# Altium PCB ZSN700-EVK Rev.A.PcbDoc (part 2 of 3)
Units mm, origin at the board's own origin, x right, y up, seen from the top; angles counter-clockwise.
Board outline 122.05 x 75.06 mm, 2 copper layers (Top Layer, Bottom Layer), stack 0 mm thick; 172 components, 135 nets, 573 pads, 599 vias.
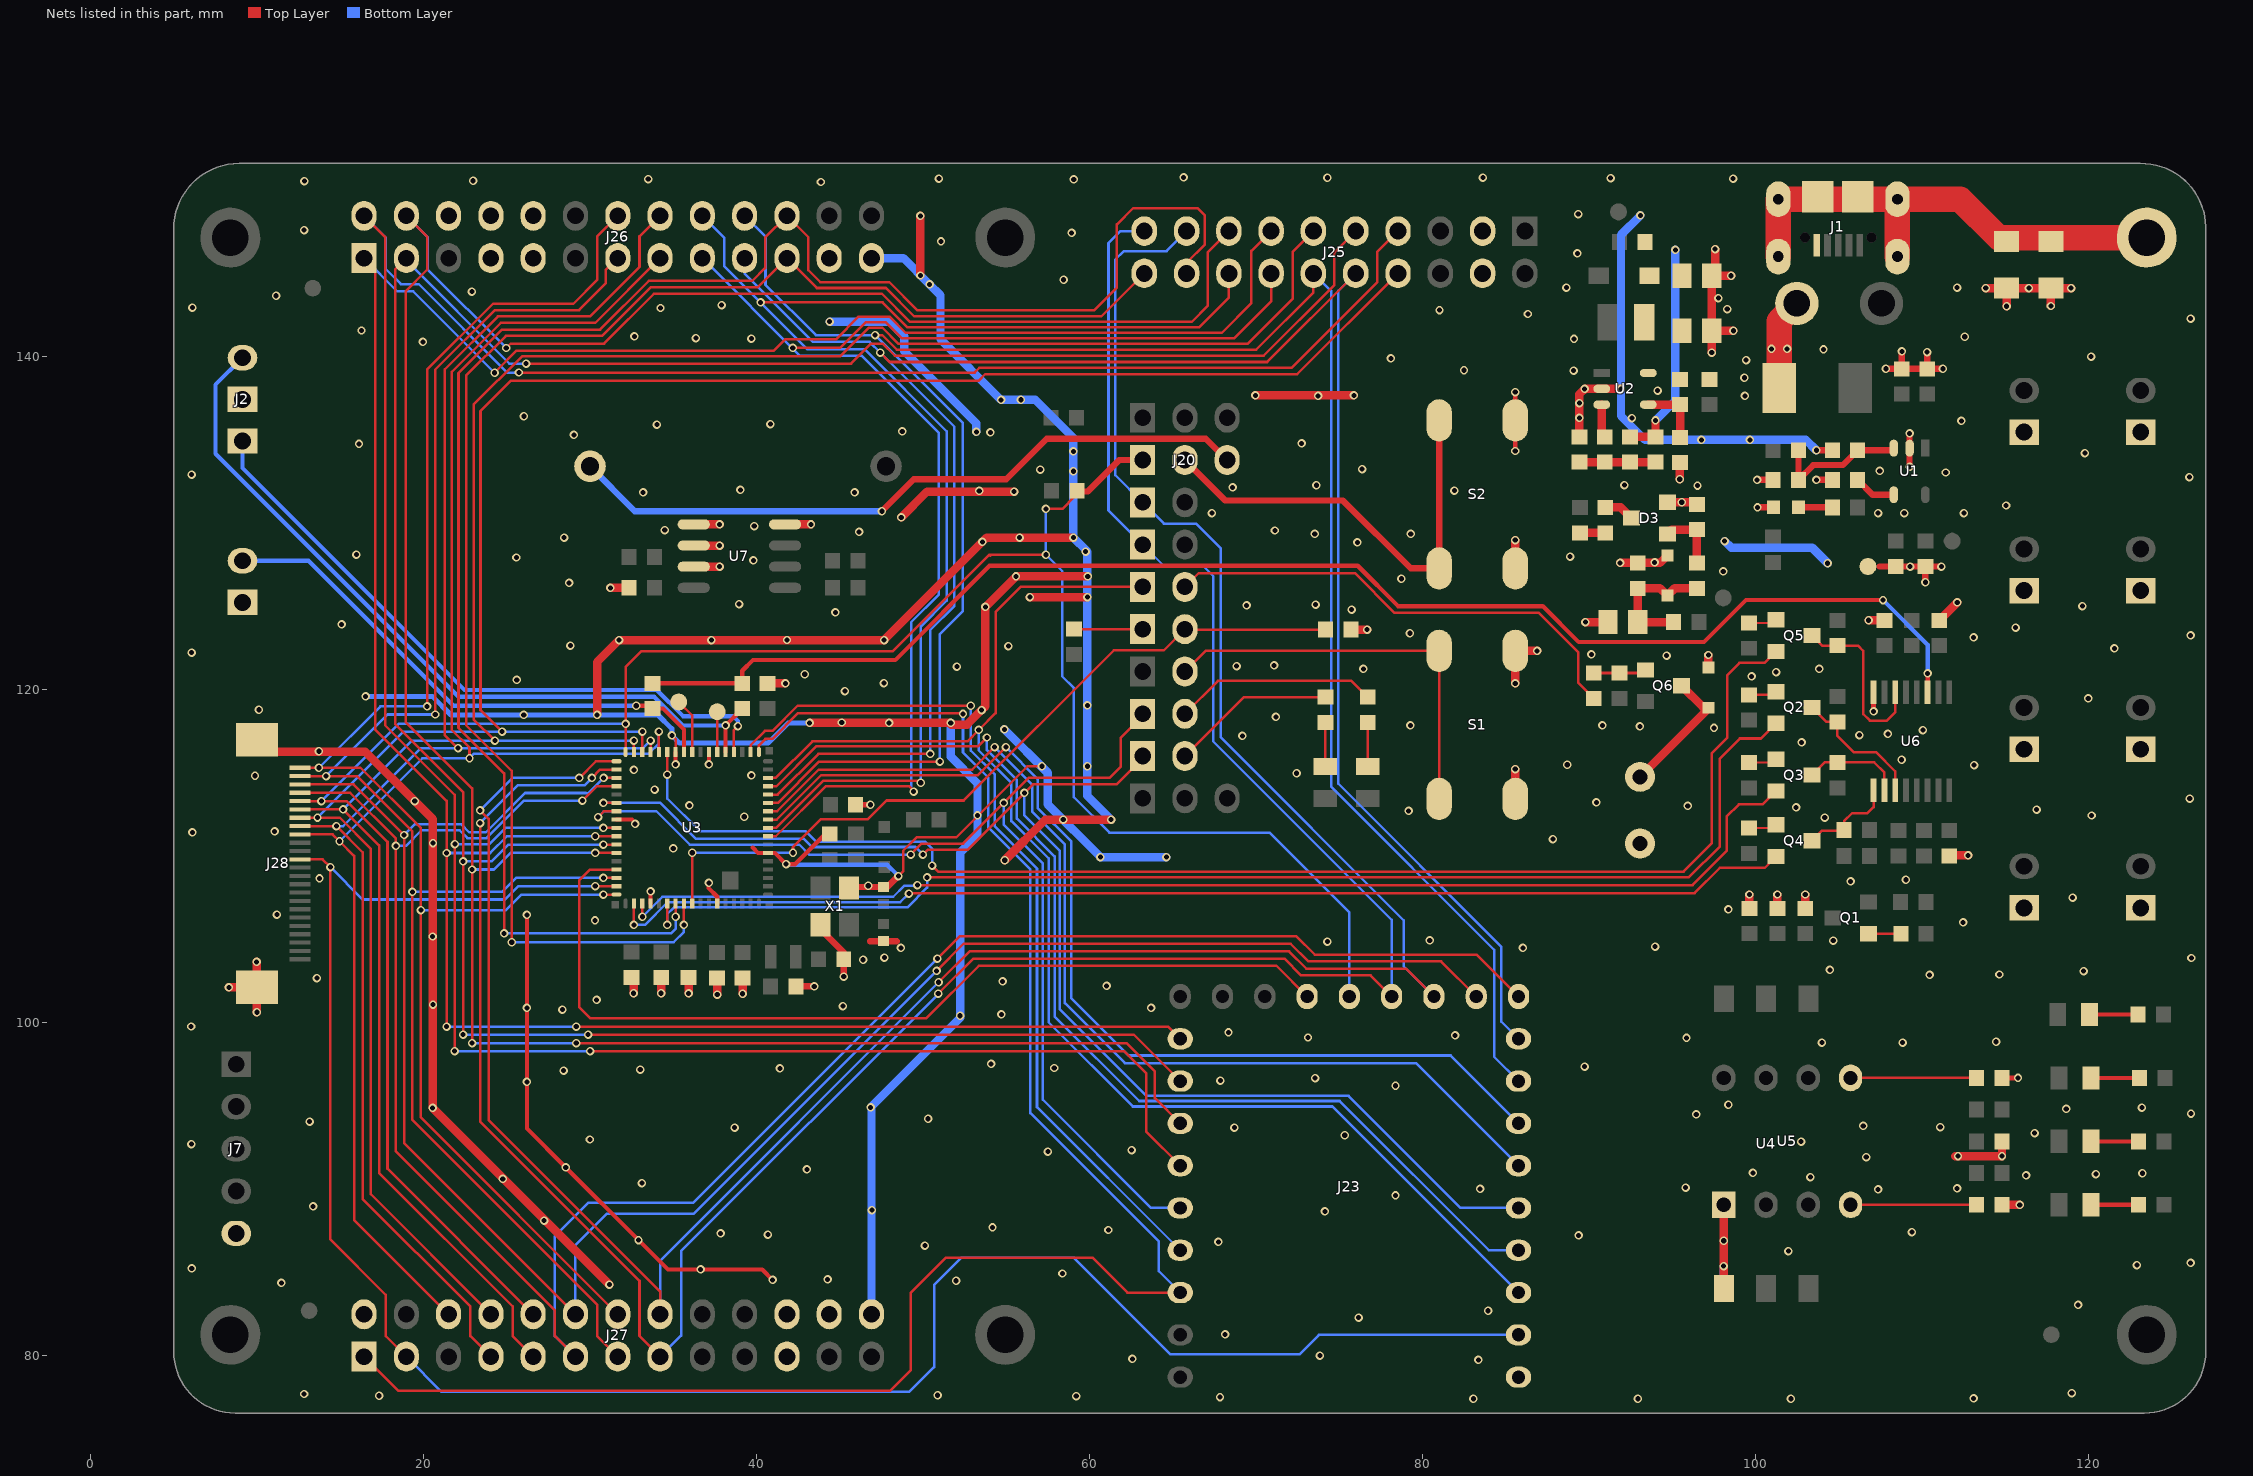
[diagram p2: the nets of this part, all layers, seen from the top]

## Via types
v1: diameter 0.508, hole 0.305, Top Layer to Bottom Layer, tented both sides, 599 vias

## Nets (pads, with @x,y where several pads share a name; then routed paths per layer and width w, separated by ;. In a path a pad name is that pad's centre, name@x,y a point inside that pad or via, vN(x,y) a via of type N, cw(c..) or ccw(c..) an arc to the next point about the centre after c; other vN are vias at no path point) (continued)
AM4051_ENN: Q5.2 U3.63 | length 82.6
  Top Layer w0.152: v1(34.643,114.909) U3.63@34.643,116.252 ; v1(50.552,109.438) 50.907,109.083 95.68,109.083 97.381,110.785 97.381,116.195 98.296,117.109 98.296,120.87 99.041,121.615 100.549,121.615 Q5.2@101.24,122.306
  Bottom Layer w0.152: v1(34.643,114.909) 34.643,113.47 36.606,111.507 42.954,111.507 43.6,110.861 50.149,110.861 50.552,110.458 v1(50.552,109.438)
AM4051_ENN1: Q5.3 R34.1 U6.6 | length 10.7
  Top Layer w0.152: Q5.3@103.399,123.256 104.009,122.646 R34.1@104.923,122.646 106.161,122.646 106.477,122.33 106.477,118.546 106.874,118.149 107.895,118.149 108.393,118.647 U6.6@108.393,119.856
AM4051_S1: Q2.2 U3.23 | length 76.7
  Top Layer w0.152: v1(34.643,105.88) U3.23@34.643,107.152 ; v1(50.247,108.727) 95.992,108.727 97.864,110.599 97.864,115.865 99.072,117.072 100.325,117.072 Q2.2@101.24,117.988
  Bottom Layer w0.152: v1(34.643,105.88) 34.643,106.519 35.056,106.932 49.062,106.932 50.247,108.116 v1(50.247,108.727)
AM4051_S2: Q3.2 U3.20 | length 73.2
  Top Layer w0.152: v1(33.143,106.369) U3.20@33.143,107.152 ; v1(49.663,108.27) 96.221,108.27 98.27,110.319 98.27,112.385 99.001,113.115 100.432,113.115 Q3.2@101.24,113.924
  Bottom Layer w0.152: v1(33.143,106.369) 34.345,107.57 48.216,107.57 48.873,108.227 49.62,108.227 v1(49.663,108.27)
AM4051_S3: Q4.2 U3.19 | length 71.6
  Top Layer w0.152: v1(32.643,105.88) U3.19@32.643,107.152 ; v1(49.155,107.762) 49.155,107.775 49.166,107.787 96.348,107.787 97.872,109.311 100.565,109.311 Q4.2@101.24,109.987
  Bottom Layer w0.152: v1(32.643,105.88) 33.301,105.88 34.658,107.237 48.629,107.237 v1(49.155,107.762)
AM4051_S11: Q2.3 R29.1 U6.11 | length 8.2
  Top Layer w0.152: Q2.3@103.399,118.938 104.263,118.074 R29.1@104.923,118.074 104.923,117.235 105.903,116.256 107.243,116.256 108.393,115.105 U6.11@108.393,113.956
AM4051_S22: Q3.3 R30.1 U6.10 | length 6
  Top Layer w0.152: Q3.3@103.399,114.874 104.161,115.636 R30.1@104.923,115.636 107.135,115.636 107.743,115.028 U6.10@107.743,113.956
AM4051_S33: Q4.3 R33.1 U6.9 | length 5.9
  Top Layer w0.152: Q4.3@103.399,110.937 104.009,111.547 105.332,111.547 R33.1@105.332,111.572 105.332,112.105 105.814,112.588 106.729,112.588 107.093,112.953 U6.9@107.093,113.956
AM4051_TX: R12.2 R13.2 U6.3 | length 86.9
  Top Layer w0.254: R13.2@33.762,120.386 R12.2@39.147,120.386 39.147,121.14 39.799,121.793 48.342,121.793 53.996,127.447 76.112,127.447 78.537,125.023 87.224,125.023 89.383,122.864 96.911,122.864 99.433,125.386 v1(107.663,125.386) ; U6.3@110.343,119.856 v1(110.343,120.98)
  Bottom Layer w0.254: v1(107.663,125.386) 110.343,122.706 v1(110.343,120.98)
ANT_TX1: T5.1 U3.57 | length 2.4
  Top Layer w0.152: T5.1@37.639,118.685 37.643,118.681 U3.57@37.643,116.252
ANT_TX2: T6.1 U3.60 | length 3.4
  Top Layer w0.152: T6.1@35.328,119.27 36.143,118.454 U3.60@36.143,116.252
BEEP: J18.2 R43.1 | length 29.1
  Top Layer w0.152: J18.2@65.731,126.178 66.565,127.012 75.938,127.012 78.334,124.616 86.995,124.616 89.35,122.262 89.35,120.427 R43.1@90.293,119.483
BOOT0: J8.2 R17.2 U3.26 | length 46.9
  Top Layer w0.152: v1(36.142,110.21) 36.142,107.154 U3.26@36.143,107.152 ; v1(42.195,110.21) 42.195,110.553 43.87,112.228 46.69,112.228 47.812,113.35 52.44,113.35 61.458,122.368 64.461,122.368 J8.2@65.731,123.638 65.758,123.612 R17.2@74.174,123.612
  Bottom Layer w0.152: v1(36.142,110.21) v1(42.195,110.21)
CAN0_RX_AWORKS: J26.9
CAN0_TX_AWORKS: J26.10
CAN1_RX_AWORKS: J26.7
CAN1_TX_AWORKS: J26.8
COM0: J26.14 J27.14 J28.1 U3.17 | length 100.1
  Top Layer w0.152: J28.1@12.575,115.316 v1(13.722,115.316) 16.215,115.316 19.839,111.691 v1(19.839,106.768) 19.839,94.321 J27.14@31.67,82.49 ; v1(20.224,119.006) 20.224,139.224 24.186,143.187 29.004,143.187 30.435,144.617 30.435,147.231 J26.14@31.67,148.466 ; v1(30.806,107.702) U3.17@31.59,107.702
  Bottom Layer w0.152: v1(13.722,115.316) 17.412,119.006 v1(20.224,119.006) ; v1(19.839,106.768) 24.946,106.768 25.881,107.702 v1(30.806,107.702)
COM1: J26.13 J27.13 J28.2 U3.15 | length 100.4
  Top Layer w0.152: J28.2@12.575,114.816 v1(14.153,114.816) 16.008,114.816 19.339,111.484 v1(19.339,107.86) 19.339,94.169 30.435,83.073 30.435,81.186 J27.13@31.67,79.95 ; v1(20.707,118.514) 20.707,139.224 24.288,142.806 29.342,142.806 30.943,144.407 30.943,145.199 J26.13@31.67,145.926 ; v1(30.806,108.702) U3.15@31.59,108.702
  Bottom Layer w0.152: v1(14.153,114.816) 17.852,118.514 v1(20.707,118.514) ; v1(19.339,107.86) 24.718,107.86 25.56,108.702 v1(30.806,108.702)
COM2: J23.11 J27.12 J28.3 U3.3 | length 122.2
  Top Layer w0.152: J28.3@12.575,114.316 15.801,114.316 v1(18.839,111.277) 18.839,92.781 J27.12@29.13,82.49 ; v1(30.821,114.702) U3.3@31.59,114.702 ; v1(50.816,103.121) 52.442,104.746 72.086,104.746 73.15,103.683 81.125,103.683 J23.11@83.232,101.576
  Bottom Layer w0.152: v1(18.839,111.277) 19.493,111.931 22.256,111.931 22.746,111.441 23.745,111.441 26.103,113.799 29.735,113.799 29.738,113.796 29.914,113.796 v1(30.821,114.702) ; J27.12@29.13,82.49 29.13,86.644 31.028,88.542 36.238,88.542 v1(50.816,103.121)
COM3: J23.10 J27.11 J28.4 U3.4 | length 132.2
  Top Layer w0.152: J28.4@12.575,113.816 15.593,113.816 18.339,111.07 v1(18.339,110.624) 18.339,92.273 27.895,82.718 27.895,81.186 J27.11@29.13,79.95 ; v1(29.546,113.342) 30.406,114.202 U3.4@31.59,114.202 ; v1(50.867,103.857) 52.213,105.203 72.416,105.203 73.531,104.089 83.259,104.089 J23.10@85.772,101.576
  Bottom Layer w0.152: v1(18.339,110.624) 18.943,110.624 19.868,111.55 22.18,111.55 22.637,111.093 23.791,111.093 26.041,113.342 v1(29.546,113.342) ; J27.11@29.13,79.95 27.895,81.186 27.895,87.187 29.911,89.203 36.213,89.203 v1(50.867,103.857)
CZ_RX: J2.1 U3.55 | length 39.6
  Top Layer w0.152: U3.55@38.643,116.252 38.643,117.572 v1(38.884,117.812)
  Bottom Layer w0.254: J2.1@9.13,134.942 9.13,133.318 22.459,119.989 34.008,119.989 35.583,118.415 38.588,118.415 38.884,118.119 v1(38.884,117.812)
CZ_TX1: J2.3 J4.2 R12.1 U3.56 | length 46.8
  Top Layer w0.254: U3.56@38.143,116.252 v1(38.143,117.858) R12.1@39.147,118.862
  Bottom Layer w0.254: J2.3@9.13,139.942 7.515,138.326 7.515,134.172 22.104,119.583 33.856,119.583 35.581,117.858 v1(38.143,117.858)
CZ_TX2: J3.2 R13.1 U3.61 | length 32.1
  Top Layer w0.152: R13.1@33.584,119.04 R13.1@33.762,118.862
  Top Layer w0.254: v1(32.78,119.04) R13.1@33.584,119.04 ; R13.1@33.775,118.874 34.388,118.874 35.643,117.619 U3.61@35.643,116.252
  Bottom Layer w0.254: J3.2@9.13,127.75 13.099,127.75 21.809,119.04 v1(32.78,119.04)
EARTH1: C1.1 HOLE4.1 J1.6 J1.7 J1.8 J1.9 J1.10 J1.11 R1.2 | length 30
  Top Layer w1.524: J1.7@101.374,146.014 J1.9@101.374,149.464 J1.8@108.524,149.464 ; J1.6@108.524,146.014 J1.8@108.524,149.464 ; HOLE4.1@123.5,147.158 114.6,147.158 112.294,149.464 J1.8@108.524,149.464
ERR_AWORKS: J26.6
GND: BZ1.2 C1.2 C2.1 C3.1 C4.1 C5.1 C6.1 C7.1 C9.2 C10.2 C12.2 C13.1 C14.2 C15.2 C16.2 C17.2 C18.2 C19.2 C20.1 C21.2 C22.2 C23.2 C24.2 C25.2 C26.2 C27.2 C28.2 C29.2 C30.2 D1.2 D3.2 D4.2 D6.1 J1.5 J2.2 J3.1 J4.1 J7.5 J9.1 J10.1 J11.1 J12.1 J13.1 J14.1 J15.1 J16.1 J23.1 J25.3 J25.4 J26.23 J26.25 J27.21 J27.26 J28.25 J28.26 J29.2 LED1.2 R1.1 R4.2 R8.1 R9.1 R11.1 R17.1 R18.2 R25.1 R26.1 R27.1 R40.1 S1.2 S1.3 S2.1 S2.4 T2.1 T8.1 U1.2 U2.2 U3.8 U3.21 U3.29 U3.40 U3.58 U3.62 U4.6 U5.1 U6.8 U7.4 U7.5 U7.6 U7.7 X1.2 X1.4 | length 469.7
  Top Layer w0.152: v1(34.915,117.262) 35.143,117.034 U3.62@35.143,116.252 ; v1(48.525,108.813) 48.808,109.096 48.808,110.33 49.618,111.14 52,111.14 56.267,115.407 v1(57.139,115.407)
  Top Layer w0.254: v1(26.21,106.477) v1(26.21,100.889) v1(26.21,96.444) 26.21,93.65 v1(28.547,91.313) v1(32.916,86.944) 34.682,85.178 40.346,85.178 v1(40.968,84.556) ; U3.8@31.59,112.202 32.526,112.202 ; U3.21@33.643,107.152 v1(33.643,107.89) ; v1(35.143,115.517) U3.62@35.143,116.252 ; 37.113,108.126 37.113,108.1 37.643,107.57 U3.29@37.643,107.152 ; v1(37.143,115.515) U3.58@37.143,116.252 ; 39.776,110.519 40.093,110.202 41.103,110.202 v1(41.781,109.525) 42.322,109.525 44.13,111.332 C19.2@44.399,111.332 ; X1.2@45.549,108.092 X1.2@45.61,108.153 ; v1(85.576,134.34) S2.1@85.576,136.183 v1(85.576,137.877)
  Top Layer w0.305: C14.2@45.958,113.096 v1(46.847,113.096) ; U5.1@98.095,89.066 U5.1@98.098,89.063 ; v1(107.093,118.696) U6.8@107.093,119.856 ; R26.1@114.808,96.686 v1(115.77,96.686)
  Top Layer w0.381: C22.2@42.379,102.185 v1(43.471,102.185) ; X1.4@43.849,105.892 43.849,105.617 45.243,104.223 C25.2@45.243,103.81 v1(45.243,102.776) ; X1.2@45.61,108.153 C21.2@47.631,108.153 47.864,108.153 v1(48.525,108.813) ; 46.823,104.902 C20.1@47.631,104.902 48.426,104.902 ; v1(100.099,132.607) R4.2@101.063,132.607 ; v1(100.123,130.956) LED1.2@101.087,130.956 ; v1(103.655,132.607) C6.1@104.619,132.607 ; v1(103.655,134.385) C7.1@104.619,134.385 ; 107.464,127.4 C4.1@108.429,127.4 v1(109.293,127.4) C5.1@110.207,127.4 ; v1(107.838,139.28) C3.1@108.792,139.28 ; v1(108.792,140.321) C3.1@108.792,139.28 ; v1(109.257,133.384) U1.2@109.257,134.512 v1(109.257,135.4) ; v1(110.207,126.46) C5.1@110.207,127.4 ; v1(110.316,140.285) C2.1@110.316,139.28 ; v1(111.172,127.4) C5.1@110.207,127.4 ; v1(111.256,139.28) C2.1@110.316,139.28 ; C3.1@108.792,139.28 C2.1@110.316,139.28
  Top Layer w0.508: v1(8.317,102.126) J28.26@10,102.126 ; v1(9.982,103.661) 9.982,102.144 J28.26@10,102.126 ; v1(10,100.631) J28.26@10,102.126 ; J28.25@10.597,116.373 10.699,116.271 16.516,116.271 v1(19.477,113.309) 20.554,112.232 v1(20.554,105.181) v1(20.554,94.884) v1(31.171,84.267) ; v1(30.427,118.489) 30.427,121.666 v1(31.748,122.987) v1(47.667,122.987) 53.818,129.137 v1(59.03,129.137) ; v1(31.227,126.124) C30.2@32.35,126.124 ; v1(32.619,101.774) C18.2@32.619,102.733 ; v1(34.277,101.774) C15.2@34.277,102.733 ; v1(35.923,101.769) C16.2@35.923,102.728 ; U7.7@36.235,127.394 v1(37.787,127.394) ; U7.6@36.235,128.664 v1(37.787,128.664) ; U7.5@36.235,129.934 v1(37.787,129.934) ; v1(37.643,101.694) C23.2@37.643,102.653 ; v1(39.163,101.744) C24.2@39.163,102.702 ; C17.2@40.671,120.386 v1(41.738,120.386) ; U7.4@41.723,129.934 v1(43.275,129.934) ; v1(43.192,118.009) 43.195,118.006 v1(51.667,118.006) ; v1(48.697,130.353) 50.251,131.906 v1(55.474,131.906) ; v1(49.84,144.881) v1(49.84,148.463) ; v1@51.689,117.908 52.655,117.908 v1(53.523,118.776) 53.752,119.005 v1(53.752,124.976) v1(55.588,126.812) v1(59.899,126.812) ; v1(54.914,109.762) 57.359,112.207 v1(58.426,112.207) v1(61.296,112.207) ; v1(56.419,125.567) v1(59.872,125.567) ; v1(69.969,137.68) v1(75.888,137.68) ; R17.1@75.698,123.612 v1(76.671,123.612) ; S1.2@85.576,113.45 v1(85.576,115.235) ; v1(85.576,120.38) S1.3@85.576,122.34 v1(86.893,122.34) ; S2.4@85.576,127.293 v1(85.576,128.99) ; R9.1@89.426,135.19 v1(89.426,136.333) v1(89.426,137.222) 89.426,137.756 v1(89.746,138.076) U2.2@90.772,138.076 v1(91.925,138.076) ; v1(89.79,124.065) C12.2@91.153,124.065 ; v1(91.873,127.621) R11.1@92.931,127.621 94.265,127.621 D4.2@94.709,128.066 ; D3.2@94.709,131.264 v1(95.576,131.264) 96.365,131.264 C13.1@96.487,131.142 ; v1(95.453,132.643) 95.453,133.623 R8.1@95.471,133.641 ; D6.1@97.177,121.337 v1(97.177,122.089) ; v1(97.376,140.245) C10.2@97.376,141.566 ; v1(97.573,146.465) 97.573,145.065 C9.2@97.376,144.868 ; U4.6@98.098,84.037 v1(98.098,86.909) U5.1@98.098,89.063 ; v1(98.544,144.868) C9.2@97.376,144.868 ; v1(98.671,141.566) C10.2@97.376,141.566 ; R18.2@99.64,106.873 v1(99.64,107.705) ; C27.2@101.316,106.873 v1(101.316,107.705) ; C26.2@102.993,106.873 v1(102.993,107.705) ; v1(106.802,124.174) C29.2@107.743,124.174 ; R40.1@111.045,124.174 v1(112.123,125.251) ; C28.2@111.643,110.019 111.682,110.058 v1(112.774,110.058) ; v1@112.014,91.986 v1(114.808,91.986) R27.1@114.808,92.876 ; v1(113.834,144.121) C1.2@115.082,144.121 ; R25.1@114.808,89.066 v1(115.874,89.066) ; v1(115.082,143.037) C1.2@115.082,144.121 ; v1(117.749,143.051) R1.1@117.749,144.121 ; v1(118.965,144.121) R1.1@117.749,144.121 ; C10.2@97.376,141.566 C9.2@97.376,144.868 ; C1.2@115.082,144.121 R1.1@117.749,144.121
  Top Layer w1.524: D1.2@101.426,138.137 101.426,142.142 J29.2@102.489,143.206
  Bottom Layer w0.254: v1(41.781,109.525) 41.816,109.489 47.849,109.489 v1(48.525,108.813)
  Bottom Layer w0.305: v1(16.525,119.606) 20.531,119.606 21.648,118.489 v1(26.025,118.489) v1(30.427,118.489) 34.088,118.489 34.915,117.661 v1(34.915,117.262) 35.384,116.793 40.686,116.793 41.903,118.009 v1(43.192,118.009)
  Bottom Layer w0.508: v1(44.389,142.111) 47.987,142.111 48.87,141.228 48.87,140.339 53.213,135.995 v1(53.213,135.487) ; J27.26@46.91,82.49 46.91,94.976 52.228,100.294 v1(52.228,100.421) 52.228,110.212 53.276,111.259 53.276,114.377 51.667,115.986 v1(51.667,118.006) ; J26.25@46.91,145.926 48.821,145.926 v1(50.399,144.348) 51.054,143.693 51.054,141.052 v1(54.692,137.414) 56.749,137.414 59.035,135.128 59.03,135.122 v1(59.03,129.137) 59.872,128.295 v1(59.872,125.567) v1(59.872,119.066) 59.872,113.631 v1(61.296,112.207) ; v1(54.895,117.617) 57.494,115.018 57.494,113.113 v1(60.661,109.946) v1(64.623,109.946) ; v1(93.091,148.492) 91.925,147.326 91.925,136.45 93.37,135.005 v1(99.67,135.005) 103.035,135.005 v1(103.655,134.385) ; v1(98.091,85.385) 98.098,85.377 T8.1@98.098,84.037 ; v1(98.146,128.934) 98.552,128.528 103.412,128.528 v1(104.341,127.599)
  other v1: 83.056,77.419 92.936,77.419 102.131,77.419 113.104,77.444 67.841,77.521 59.207,77.575 17.335,77.598 50.876,77.626 12.827,77.702 119,77.758 83.36,79.756 62.583,79.807 73.835,80.01 68.146,81.28 76.172,82.296 83.945,82.702 119.378,83.058 11.467,84.38 51.991,84.506 44.27,84.582 58.369,84.941 36.65,85.191 6.083,85.243 122.911,85.449 126.134,85.572 101.981,86.288 50.112,86.614 67.739,86.842 89.383,87.227 40.688,87.274 37.844,87.35 109.398,87.431 61.135,87.554 54.176,87.706 27.252,88.112 74.14,88.671 46.937,88.747 13.372,88.977 78.382,89.636 107.366,89.996 83.462,90.017 112.116,90.047 95.809,90.098 33.119,90.373 24.763,90.627 103.302,90.733 116.256,90.834 120.447,90.91 123.241,90.961 99.847,90.987 43.028,91.19 106.655,91.926 112.166,91.986 57.5,92.258 62.532,92.354 6.057,92.711 102.743,92.866 29.995,92.989 75.334,93.243 116.764,93.374 38.684,93.704 68.705,93.7 111.1,93.73 106.477,93.806 13.157,94.06 50.315,94.234 96.444,94.492 126.162,94.543 118.669,94.822 123.215,94.898 46.861,94.92 98.374,95.076 78.382,96.215 67.866,96.52 73.556,96.672 28.42,97.129 33.02,97.184 41.402,97.26 57.884,97.282 89.738,97.362 54.1,97.536 103.988,98.81 108.839,98.81 114.452,98.861 95.86,99.089 73.127,99.115 81.966,99.242 68.351,99.419 6.045,99.775 54.709,100.508 28.344,100.787 63.701,100.889 45.187,100.994 20.572,101.092 30.404,101.375 61.034,102.209 54.785,102.489 13.603,102.682 110.465,102.874 114.656,102.899 119.71,103.102 104.47,103.179 46.402,103.786 126.187,103.89 47.68,103.909 48.67,104.493 86.027,104.495 93.978,104.572 74.293,104.876 104.673,104.931 80.439,104.953 112.471,106.023 30.302,106.15 11.19,106.492 98.372,106.807 119.047,107.518 46.714,108.227 37.139,108.405 105.715,108.487 109.042,108.589 13.756,108.676 35.001,110.468 20.572,110.788 87.833,111.027 6.121,111.434 11.063,111.496 32.715,111.942 104.165,112.323 39.268,112.373 53.276,112.451 120.193,112.45 79.172,112.729 116.888,112.801 102.438,112.932 95.933,113.03 35.966,113.059 90.449,113.237 126.086,113.466 33.884,113.999 9.881,114.837 39.7,114.863 72.438,114.986 32.639,115.193 59.872,115.407 113.132,115.472 88.697,115.498 108.786,115.798 13.714,116.306 102.768,116.844 69.19,117.225 106.248,117.276 107.95,117.352 110.058,117.58 97.511,117.707 93.063,117.805 79.271,117.856 90.803,117.856 47.967,118.009 45.122,118.035 71.196,118.368 10.109,118.8 119.99,119.485 45.314,119.917 47.65,120.4 25.601,120.599 99.769,120.802 42.901,120.933 101.244,121.06 76.452,121.259 103.833,121.259 52.042,121.386 68.834,121.416 71.095,121.467 94.666,122.051 90.145,122.127 6.071,122.229 121.564,122.483 55.132,122.621 28.827,122.656 37.287,122.987 41.834,122.991 113.106,123.143 126.136,123.27 79.248,123.397 115.632,123.732 15.088,123.93 44.744,124.653 75.743,124.819 119.634,125.023 69.441,125.069 73.581,125.12 38.964,125.15 28.75,126.416 78.738,126.67 98.069,127.105 93.947,127.652 39.816,127.777 25.578,127.944 88.875,127.994 15.974,128.117 59.766,128.299 76.096,128.854 53.569,128.888 28.448,129.137 55.804,129.137 73.531,129.362 79.296,129.362 46.166,129.479 71.143,129.565 34.493,129.595 39.867,129.835 67.358,130.607 107.366,130.611 108.941,130.611 112.526,130.605 115.062,131.068 33.194,131.857 45.894,131.857 53.38,131.943 81.915,131.957 39.036,132.009 68.603,132.156 96.52,132.262 73.632,132.283 92.126,132.287 126.06,132.77 6.071,132.922 111.43,133.049 59.03,133.125 107.467,133.151 57.045,133.228 76.375,133.248 119.786,134.217 59.03,134.319 16.127,134.772 72.743,134.798 96.749,135.005 29.032,135.31 54.047,135.463 48.757,135.524 34.025,135.931 40.832,135.956 112.37,136.148 92.581,136.322 26.035,136.427 55.876,137.419 73.729,137.654 99.365,137.646 94.13,137.973 99.339,138.739 89.078,139.17 82.497,139.192 99.441,139.805 78.103,139.903 120.167,140.009 104.089,140.44 100.965,140.476 101.905,140.476 19.962,140.894 89.103,141.075 39.69,141.095 36.362,141.12 112.573,141.202 32.668,141.222 16.279,141.579 126.136,142.295 86.332,142.57 81.024,142.799 98.31,142.858 34.235,142.931 6.121,142.955 37.912,143.101 97.776,143.519 11.151,143.666 22.908,143.916 116.422,144.124 88.646,144.149 112.116,144.149 58.449,144.625 89.306,146.206 51.083,146.937 58.932,147.445 12.827,147.603 89.357,148.568 43.866,150.499 12.852,150.55 22.987,150.575 59.055,150.651 33.503,150.677 50.956,150.696 98.665,150.707 91.299,150.732 74.295,150.753 83.628,150.758 65.659,150.778
GPIO4_AWORKS: J20.1 J23.14 J27.10 J28.5 R48.1 U3.68 | length 141.3
  Top Layer w0.152: J28.5@12.575,113.316 v1(13.873,113.316) 15.386,113.316 17.839,110.863 17.839,91.241 J27.10@26.59,82.49 ; U3.68@32.143,116.252 v1(32.143,117.947) 32.143,121.358 33.102,122.316 48.194,122.316 53.995,128.117 54.048,128.065 54.091,128.108 v1(57.379,128.108) ; v1(57.379,130.865) 58.37,130.865 59.106,131.6 ccw(c58.748,131.958) 59.252,131.906 ccw(c58.748,131.958) R48.1@59.254,131.958
  Top Layer w0.381: R48.1@59.252,131.906 59.893,131.906 61.786,133.798 J20.1@63.191,133.798
  Bottom Layer w0.152: v1(13.873,113.316) 18.505,117.947 v1(32.143,117.947) ; v1(57.379,130.865) v1(57.379,128.108) 58.365,127.121 58.365,120.808 59.069,120.104 59.069,113.545 61.194,111.42 70.813,111.42 75.612,106.621 J23.14@75.612,101.576
GPIO5_AWORKS: J25.11 J27.9 J28.6 U3.67 | length 138
  Top Layer w0.152: J28.6@12.575,112.816 v1(15.179,112.816) 17.339,110.656 17.339,90.987 25.355,82.972 25.355,81.186 J27.9@26.59,79.95 ; v1(24.288,116.949) 23.018,118.219 23.018,137.124 25.939,140.045 45.041,140.045 46.751,141.755 47.556,141.755 48.533,140.778 69.503,140.778 72.218,143.493 72.218,146.315 J25.11@73.453,147.55 ; U3.67@32.643,116.252 v1(32.643,116.949)
  Bottom Layer w0.152: v1(15.179,112.816) 19.312,116.949 v1(24.288,116.949) v1(32.643,116.949)
GPIO6_AWORKS: J25.8 J27.8 J28.7 U3.66 | length 137.2
  Top Layer w0.152: J28.7@12.575,112.316 v1(13.636,112.316) 14.972,112.316 16.839,110.449 16.839,89.701 J27.8@24.05,82.49 ; v1(24.72,117.482) 23.424,118.777 23.424,136.743 25.253,138.572 53.361,138.572 53.738,138.95 72.472,138.95 J25.8@78.533,145.01 ; U3.66@33.143,116.252 v1(33.143,117.482)
  Bottom Layer w0.152: v1(13.636,112.316) 18.802,117.482 v1(24.72,117.482) v1(33.143,117.482)
GPIO7_AWORKS: J26.16 J27.7 J28.8 U3.65 | length 100.5
  Top Layer w0.152: J28.8@12.575,111.816 v1(14.765,111.816) 16.339,110.242 16.339,89.422 22.815,82.946 22.815,81.186 J27.7@24.05,79.95 ; v1@22.068,116.481 21.291,117.258 21.291,139.25 24.466,142.425 29.995,142.425 32.975,145.405 32.975,147.231 J26.16@34.21,148.466 ; U3.65@33.643,116.252 v1(33.643,116.949)
  Bottom Layer w0.152: v1(14.765,111.816) 15.183,111.816 19.859,116.491 v1(22.078,116.491) 33.186,116.491 v1(33.643,116.949)
GPIO8_AWORKS: J26.15 J27.6 J28.9 U3.64 | length 96.2
  Top Layer w0.152: J28.9@12.575,111.316 14.545,111.316 v1(14.957,110.903) 15.839,110.021 15.839,88.161 J27.6@21.51,82.49 ; v1(22.764,115.886) 22.764,116.521 21.697,117.588 21.697,139.097 24.644,142.044 30.328,142.044 J26.15@34.21,145.926 ; U3.64@34.143,116.252 v1(34.143,117.482)
  Bottom Layer w0.152: v1(14.957,110.903) 19.94,115.886 v1(22.764,115.886) 23.039,116.161 33.531,116.161 34.143,116.773 v1(34.143,117.482)
GPIO11_AWORKS: J23.2 J27.3 J28.12 U3.16 | length 128.4
  Top Layer w0.152: J28.12@12.575,109.816 13.937,109.816 v1(14.407,109.345) 14.407,86.985 17.735,83.657 17.735,81.186 J27.3@18.97,79.95 ; v1(30.318,108.202) U3.16@31.59,108.202
  Bottom Layer w0.152: v1(14.407,109.345) 16.35,107.403 24.895,107.403 25.695,108.202 v1(30.318,108.202) ; J27.3@18.97,79.95 21.095,77.825 49.172,77.825 50.671,79.324 50.671,84.26 52.288,85.877 59.078,85.877 64.869,80.086 72.616,80.086 73.786,81.256 J23.2@85.772,81.256
GPIO12_AWORKS: J27.2
GPIO_LED0: J17.1 J23.5 U3.6 | length 83.4
  Top Layer w0.152: v1(30.806,113.202) U3.6@31.59,113.202 ; v1(50.001,110.099) 50.306,110.404 52.697,110.404 v1(56.095,113.802) 56.608,114.315 61.632,114.315 63.191,115.875 J17.1@63.191,116.018
  Bottom Layer w0.152: v1(30.806,113.202) 34.225,113.202 36.378,111.049 42.854,111.049 43.346,110.556 49.544,110.556 v1(50.001,110.099) ; v1(56.095,113.802) 56.095,112.455 58.228,110.321 58.228,100.798 63.421,95.605 75.563,95.605 82.292,88.876 J23.5@85.772,88.876
GPIO_LED1: J19.1 J23.23 U3.7 | length 69.6
  Top Layer w0.152: v1(30.486,112.351) 30.837,112.702 U3.7@31.59,112.702 ; v1(49.265,110.099) 49.925,110.759 52.406,110.759 v1(54.851,113.204) 56.368,114.722 61.225,114.722 61.874,115.371 61.874,117.098 J19.1@63.191,118.415 ; J19.1@63.191,118.368 J19.1@63.191,118.415 ; J19.1@63.191,118.558 J19.1@63.191,118.415
  Bottom Layer w0.152: v1(30.486,112.351) 30.837,112.702 33.988,112.702 35.997,110.693 42.574,110.693 43.169,110.099 v1(49.265,110.099) ; v1(54.851,113.204) 54.851,111.921 57.205,109.567 57.205,95.374 63.703,88.876 J23.23@65.452,88.876
HPR_AWORKS: J27.24
I2C0_SCL_AWORKS: J21.1 J23.12 J25.17 J27.16 U3.1 | length 161
  Top Layer w0.152: v1(23.399,112.758) 23.907,112.25 23.907,94.173 34.21,83.87 J27.16@34.21,82.49 ; v1(29.359,114.713) 30.347,115.702 U3.1@31.59,115.702 ; v1(50.943,102.435) 52.798,104.289 71.984,104.289 73.023,103.251 79.017,103.251 J23.12@80.692,101.576
  Bottom Layer w0.152: v1(23.399,112.758) 25.355,114.713 v1(29.359,114.713) ; J27.16@34.21,82.49 34.21,85.701 v1(50.943,102.435) ; J25.17@65.833,147.55 64.634,146.351 62.069,146.351 61.55,145.833 61.55,132.9 J21.1@63.191,131.258 64.467,129.983 66.407,129.983 67.892,128.498 67.892,117.135 78.879,106.148 78.879,103.389 J23.12@80.692,101.576
I2C0_SDA_AWORKS: J22.1 J23.13 J25.19 J27.15 U3.2 | length 160
  Top Layer w0.152: v1(23.399,111.996) 23.399,94.071 32.975,84.496 32.975,81.186 J27.15@34.21,79.95 ; v1(30.121,114.713) 30.609,115.202 U3.2@31.59,115.202 ; v1(50.918,101.749) 53.026,103.857 71.705,103.857 72.716,102.846 76.882,102.846 J23.13@78.152,101.576
  Bottom Layer w0.152: v1(23.399,111.996) 25.66,114.256 29.663,114.256 v1(30.121,114.713) ; J27.15@34.21,79.95 35.475,81.215 35.475,86.28 v1@50.956,101.762 ; J25.19@63.293,147.55 61.87,147.55 61.143,146.823 61.143,130.766 J22.1@63.191,128.718 64.461,127.448 66.808,127.448 67.435,126.822 67.435,116.906 78.152,106.189 J23.13@78.152,101.576
LED0: J17.2 R42.2 | length 9.9
  Top Layer w0.152: J17.2@65.731,116.018 69.276,119.563 R42.2@74.172,119.563
LED1: J19.2 R44.2 | length 12.2
  Top Layer w0.152: J19.2@65.731,118.558 67.713,120.54 75.735,120.54 R44.2@76.712,119.563
MIC_AWORKS: J27.22
MICROPORT_CS: J23.22 J25.7 J26.2 U3.9 | length 182.7
  Top Layer w0.152: J26.2@16.43,148.466 17.7,147.196 17.7,117.868 21.875,113.693 v1(21.875,98.296) ; v1(25.736,139.055) 53.107,139.055 53.383,139.331 72.145,139.331 77.298,144.483 77.298,146.315 J25.7@78.533,147.55 ; v1(30.012,98.296) 62.083,98.296 63.42,96.959 63.42,93.448 J23.22@65.452,91.416 ; v1(30.806,111.702) U3.9@31.59,111.702
  Bottom Layer w0.152: J26.2@16.43,148.466 17.735,147.162 17.735,145.278 18.649,144.363 19.716,144.363 25.025,139.055 v1(25.736,139.055) ; v1(21.875,98.296) v1(30.012,98.296) ; v1(21.887,110.726) 23.953,110.726 24.93,111.702 v1(30.806,111.702)
MICROPORT_CTS: J23.7 U3.44 | length 62.8
  Top Layer w0.152: U3.44@40.69,112.202 41.22,112.202 43.892,114.874 53.303,114.874 v1(54.98,116.55)
  Bottom Layer w0.152: v1(54.98,116.55) 56.883,114.647 56.883,112.912 58.914,110.88 58.914,101.465 62.345,98.034 81.694,98.034 J23.7@85.772,93.956
MICROPORT_DAC: J23.15 U3.14 | length 56.2
  Top Layer w0.152: U3.14@31.59,109.202 30.002,109.202 29.343,108.543 29.343,100.947 30.014,100.276 50.207,100.276 53.356,103.425 71.223,103.425 J23.15@73.072,101.576
MICROPORT_MISO: J23.20 J25.9 J26.3 U3.11 | length 167.3
  Top Layer w0.152: J26.3@18.97,145.926 18.294,145.25 18.294,117.944 22.383,113.854 v1(22.383,109.689) v1(22.383,99.286) ; v1(26.168,139.588) 45.69,139.588 46.892,140.79 47.582,140.79 48.305,140.067 70.469,140.067 74.707,144.305 74.707,146.264 J25.9@75.993,147.55 ; v1(29.885,99.286) 62.662,99.286 J23.20@65.452,96.496 ; v1(30.806,110.702) U3.11@31.59,110.702
  Bottom Layer w0.152: J26.3@18.97,145.926 18.97,145.77 25.152,139.588 v1(26.168,139.588) ; v1(22.383,99.286) v1(29.885,99.286) ; v1(22.383,109.689) 24.083,109.689 25.096,110.702 v1(30.806,110.702)
MICROPORT_MOSI: J23.21 J25.15 J26.4 U3.12 | length 167
  Top Layer w0.152: J26.4@18.97,148.466 20.224,147.212 20.224,145.227 18.929,143.932 18.929,118.071 22.916,114.083 v1(22.916,109.206) v1(22.916,98.778) ; v1(24.974,140.528) 25.241,140.796 30.855,140.796 33.847,143.787 47.531,143.787 49.219,142.099 66.144,142.099 67.112,143.068 67.112,146.289 J25.15@68.373,147.55 ; v1(29.174,98.778) 62.235,98.778 63.928,97.086 63.928,95.48 J23.21@65.452,93.956 ; v1(30.318,110.202) U3.12@31.59,110.202
  Bottom Layer w0.152: J26.4@18.97,148.466 20.249,147.187 20.249,145.252 v1(24.974,140.528) ; v1(22.916,98.778) v1(29.174,98.778) ; v1(22.916,109.206) 24.235,109.206 25.231,110.202 v1(30.318,110.202)
MICROPORT_PWM0: J18.1 J23.3 U3.49 | length 85.1
  Top Layer w0.152: U3.49@40.69,114.702 41.155,114.702 43.359,116.906 52.666,116.906 v1(53.352,117.592) 54.362,118.601 54.362,124.678 55.862,126.178 J18.1@63.191,126.178
  Bottom Layer w0.152: v1(53.352,117.592) 53.352,116.358 55.308,114.403 55.308,112.118 57.555,109.871 57.555,100.024 62.609,94.97 74.598,94.97 J23.3@85.772,83.796
MICROPORT_PWM1: J23.4 U3.48 | length 66.5
  Top Layer w0.152: U3.48@40.69,114.202 41.188,114.202 43.587,116.601 53.301,116.601 v1(53.835,117.135)
  Bottom Layer w0.152: v1(53.835,117.135) 53.835,116.374 55.638,114.571 55.638,112.265 57.904,109.999 57.904,100.386 62.99,95.301 75.029,95.301 83.994,86.336 J23.4@85.772,86.336
MICROPORT_PWM2: J23.25 J27.1 U3.52 | length 110.4
  Top Layer w0.152: J27.1@16.43,79.95 18.489,77.892 48.019,77.892 49.274,79.146 49.274,83.794 51.356,85.877 60.202,85.877 62.283,83.796 J23.25@65.452,83.796 ; U3.52@40.143,116.252 40.143,116.658 40.536,117.05 40.963,117.05 42.506,118.594 52.369,118.594 v1(52.406,118.557)
  Bottom Layer w0.152: v1(52.406,118.557) 52.406,116.238 53.928,114.716 53.928,111.726 56.449,109.204 56.449,94.581 64.172,86.858 64.172,85.076 J23.25@65.452,83.796
MICROPORT_PWM3: J23.24 U3.53 | length 52.5
  Top Layer w0.152: U3.53@39.643,116.252 39.643,116.667 40.509,117.533 40.963,117.533 42.47,119.04 v1(52.871,119.04)
  Bottom Layer w0.152: v1(52.871,119.04) 52.871,116.345 54.317,114.899 54.317,111.794 56.849,109.261 56.849,94.938 J23.24@65.452,86.336
MICROPORT_RTS: J23.6 U3.45 | length 63.6
  Top Layer w0.152: U3.45@40.69,112.702 41.238,112.702 43.74,115.204 52.959,115.204 v1(54.305,116.55)
  Bottom Layer w0.152: v1(54.305,116.55) 56.552,114.303 56.552,112.683 58.527,110.708 58.527,101.185 62.136,97.577 79.611,97.577 J23.6@85.772,91.416
MICROPORT_RXD: J23.9 J25.10 J26.19 U3.47 | length 130.2
  Top Layer w0.152: U3.47@40.69,113.702 41.273,113.702 43.714,116.144 v1(50.437,116.144) ; v1(47.437,140.252) 48.003,139.686 70.669,139.686 J25.10@75.993,145.01
  Bottom Layer w0.152: J26.19@39.29,145.926 39.29,145.008 43.4,140.898 46.792,140.898 v1(47.437,140.252) 51.892,135.797 51.892,125.034 50.437,123.579 v1(50.437,116.144) ; J25.10@75.993,145.01 74.942,143.959 74.942,114.366 84.746,104.562 84.746,100.062 J23.9@85.772,99.036
MICROPORT_SCK: J23.19 J25.13 J26.1 U3.10 | length 166.7
  Top Layer w0.152: J26.1@16.43,145.926 17.1,145.257 17.1,117.62 21.392,113.327 v1(21.392,110.197) v1(21.392,99.769) ; v1(24.275,139.042) 25.599,140.366 41.043,140.366 41.722,141.044 44.77,141.044 46.141,142.416 47.988,142.416 48.965,141.439 67.947,141.439 69.729,143.22 69.729,146.366 J25.13@70.913,147.55 ; v1(29.174,99.769) 64.719,99.769 J23.19@65.452,99.036 ; v1(30.318,111.202) U3.10@31.59,111.202
  Bottom Layer w0.152: J26.1@16.43,145.926 18.425,143.932 19.386,143.932 v1(24.275,139.042) ; v1(21.392,99.769) v1(29.174,99.769) ; v1(21.392,110.197) 24.009,110.197 25.014,111.202 v1(30.318,111.202)
MICROPORT_TXD: J23.8 J25.12 J26.20 U3.46 | length 135.1
  Top Layer w0.152: U3.46@40.69,113.202 41.281,113.202 43.765,115.687 v1(51.012,115.687) ; v1(47.123,141.298) 47.556,141.298 48.432,140.423 70.011,140.423 73.453,143.865 J25.12@73.453,145.01
  Bottom Layer w0.152: J26.20@39.29,148.466 40.544,147.212 40.544,144.321 43.567,141.298 v1(47.123,141.298) 52.4,136.021 52.4,124.729 51.012,123.341 v1(51.012,115.687) ; J25.12@73.453,145.01 74.51,143.953 74.51,114.187 84.315,104.383 84.315,97.953 J23.8@85.772,96.496
MINIPORT_I/O4: J25.14 J26.17 U3.42 | length 83.5
  Top Layer w0.152: U3.42@40.69,111.202 41.16,111.202 44.171,114.214 49.15,114.214 49.48,113.883 v1(49.437,113.883) ; v1(42.179,140.536) 45.024,140.536 46.573,142.085 47.76,142.085 48.736,141.109 68.69,141.109 70.913,143.332 J25.14@70.913,145.01
  Bottom Layer w0.152: J26.17@36.75,145.926 42.617,140.059 46.327,140.059 50.952,135.434 50.952,125.715 49.291,124.054 49.291,114.072 49.48,113.883 v1(49.437,113.883)
MINIPORT_I/O5: J25.16 J26.18 U3.43 | length 84.3
  Top Layer w0.152: v1(40.249,143.262) 47.574,143.262 49.067,141.769 66.575,141.769 68.373,143.566 J25.16@68.373,145.01 ; U3.43@40.69,111.702 41.178,111.702 44.019,114.544 49.742,114.544 v1(49.869,114.417)
  Bottom Layer w0.152: J26.18@36.75,148.466 38.055,147.162 38.055,145.456 v1(40.249,143.262) 43.045,140.466 46.482,140.466 51.43,135.518 51.43,125.359 49.881,123.81 49.881,114.329 49.869,114.341 v1(49.869,114.417)
MINIPORT_I/O6: J25.18 J26.22 U3.24 | length 108.9
  Top Layer w0.152: v1(24.847,105.371) 24.847,114.972 22.104,117.715 22.104,139.021 24.72,141.637 30.605,141.637 33.534,144.567 39.757,144.567 40.519,145.329 40.519,147.155 J26.22@41.83,148.466 43.109,147.187 43.109,145.21 43.833,144.487 47.974,144.487 49.68,142.781 60.273,142.781 61.651,144.16 61.651,147.945 62.631,148.924 66.489,148.924 66.935,148.478 66.935,146.751 65.833,145.649 J25.18@65.833,145.01 ; v1(35.143,106.369) U3.24@35.143,107.152
  Bottom Layer w0.152: v1(24.847,105.371) 34.878,105.371 35.143,105.636 v1(35.143,106.369)
MINIPORT_I/O7: J25.20 J26.21 U3.25 | length 93.6
  Top Layer w0.152: v1(25.304,104.837) 25.304,115.124 22.561,117.868 22.561,138.869 24.948,141.256 30.732,141.256 33.644,144.168 40.072,144.168 J26.21@41.83,145.926 43.625,144.131 47.771,144.131 49.477,142.426 60.709,142.426 J25.20@63.293,145.01 ; v1(35.643,105.88) U3.25@35.643,107.152
  Bottom Layer w0.152: v1(25.304,104.837) 35.03,104.837 35.643,105.451 v1(35.643,105.88)
NetBZ1_1: BZ1.1 D6.2 Q6.3 | length 8
  Top Layer w0.508: BZ1.1@93.069,114.771 97.177,118.878 D6.2@97.177,118.924 96.872,118.924 Q6.3@95.551,120.245
NetC6_2: C6.2 U1.4 | length 2.5
  Top Layer w0.381: C6.2@106.143,132.607 107.032,131.718 U1.4@108.307,131.718
NetC7_2: C7.2 R2.2 R4.1 U1.3 | length 8.3
  Top Layer w0.381: R2.2@102.587,134.385 R4.1@102.587,132.607 103.476,133.496 105.254,133.496 C7.2@106.143,134.385 108.18,134.385 U1.3@108.307,134.512
NetC8_1: C8.1 C9.1 D2.2 R5.2 R50.1 | length 13.2
  Top Layer w0.508: R5.2@92.474,135.19 C8.1@93.998,135.19 v1(93.998,136.181)
  Bottom Layer w0.508: v1(93.998,136.181) 95.192,137.375 v1(95.192,146.417)
NetC8_2: C8.2 R5.1 R7.1 R9.2 | length 4.6
  Top Layer w0.508: R9.2@89.426,133.666 R7.1@90.95,133.666 R5.1@92.474,133.666 C8.2@93.998,133.666
NetC10_1: C10.1 L1.1 R6.2 R49.2 U2.5
NetC11_1: C11.1 R52.2 | length 1.5
  Top Layer w0.508: R52.2@89.455,129.43 90.928,129.43 C11.1@90.979,129.379
NetC11_2: C11.2 D3.3 | length 1.8
  Top Layer w0.508: C11.2@90.979,130.954 91.91,130.954 D3.3@92.55,130.314
NetC12_1: C12.1 D4.1 R10.2 R11.2 R51.1 | length 8.1
  Top Layer w0.508: R51.1@95.09,124.065 C12.1@92.931,124.065 R11.2@92.931,126.097 94.265,126.097 D4.1@94.709,125.653 95.154,126.097 R10.2@96.487,126.097
NetC13_2: C13.2 D3.1 R10.1 | length 3.9
  Top Layer w0.508: D3.1@94.709,129.364 94.963,129.618 C13.2@96.487,129.618 R10.1@96.487,127.621
NetJ6_2: J6.2 S1.1 S1.4 | length 24.7
  Top Layer w0.152: J6.2@65.731,121.098 66.973,122.34 S1.4@81.004,122.34 S1.1@81.004,113.45
NetJ8_1: J8.1 R16.1 | length 4.1
  Top Layer w0.152: R16.1@59.067,123.638 J8.1@63.191,123.638
NetJ20_2: J20.2 S2.2 S2.3 | length 26.9
  Top Layer w0.381: J20.2@65.731,133.798 68.161,131.369 75.214,131.369 79.289,127.293 S2.3@81.004,127.293 S2.2@81.004,136.183
NetJ20_3: J20.3 R47.2 | length 41.7
  Top Layer w0.381: v1(47.53,130.724) 49.449,132.643 55.011,132.643 57.444,135.075 66.995,135.075 J20.3@68.271,133.798
  Bottom Layer w0.381: R47.2@30.003,133.417 32.697,130.724 v1(47.53,130.724)
NetLED1_1: LED1.1 R3.1 | length 2
  Top Layer w0.381: LED1.1@102.587,130.956 R3.1@104.619,130.956
NetLED2_1: LED2.1 R20.1 | length 2.8
  Top Layer w0.254: LED2.1@120.118,100.496 R20.1@122.95,100.496
NetLED3_1: LED3.1 R21.1 | length 2.8
  Top Layer w0.254: LED3.1@120.151,92.876 R21.1@122.984,92.876
NetLED4_1: LED4.1 R24.1 | length 2.8
  Top Layer w0.254: LED4.1@120.151,89.066 R24.1@122.984,89.066
NetLED5_1: LED5.1 R28.1 | length 2.8
  Top Layer w0.254: LED5.1@120.194,96.686 R28.1@123.027,96.686
NetLED6_2: LED6.2 R42.1 | length 2.7
  Top Layer w0.152: LED6.2@74.172,115.381 R42.1@74.172,118.039
NetLED7_2: LED7.2 R44.1 | length 2.7
  Top Layer w0.152: LED7.2@76.712,115.381 R44.1@76.712,118.039
NetQ1_1: Q1.1 R19.2 | length 1.9
  Top Layer w0.152: Q1.1@106.803,105.349 R19.2@108.73,105.349
NetQ2_1: Q2.1 R31.1 | length 1.7
  Top Layer w0.13: R31.1@99.615,119.7 101.052,119.7 Q2.1@101.24,119.888
NetQ3_1: Q3.1 R32.1 | length 1.7
  Top Layer w0.13: R32.1@99.615,115.636 101.052,115.636 Q3.1@101.24,115.824
NetQ4_1: Q4.1 R35.1 | length 1.7
  Top Layer w0.13: R35.1@99.615,111.699 101.052,111.699 Q4.1@101.24,111.887
NetQ5_1: Q5.1 R36.1 | length 1.7
  Top Layer w0.13: R36.1@99.615,124.018 101.052,124.018 Q5.1@101.24,124.206
NetQ6_1: Q6.1 R41.1 R43.2 | length 3.2
  Top Layer w0.152: R43.2@90.293,121.007 R41.1@91.843,121.007 93.204,121.007 Q6.1@93.392,121.195
NetR6_1: R6.1 R8.2 U2.4 | length 3.7
  Top Layer w0.508: U2.4@93.566,137.126 93.571,137.121 R6.1@95.471,137.121 R8.2@95.471,135.343
NetR7_2: R7.2 U2.3 | length 2
  Top Layer w0.508: U2.3@90.772,137.126 90.772,135.368 R7.2@90.95,135.19
NetR25_2: R25.2 U5.4 | length 7.6
  Top Layer w0.152: U5.4@105.715,89.066 R25.2@113.284,89.066
NetR26_2: R26.2 U5.5 | length 7.6
  Top Layer w0.152: U5.5@105.715,96.686 R26.2@113.284,96.686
